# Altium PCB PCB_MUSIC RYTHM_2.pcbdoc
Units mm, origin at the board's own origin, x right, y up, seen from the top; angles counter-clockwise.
Board outline 75.42 x 40.06 mm, 2 copper layers (Top Layer, Bottom Layer); 25 components, 17 nets, 57 pads, 0 vias.
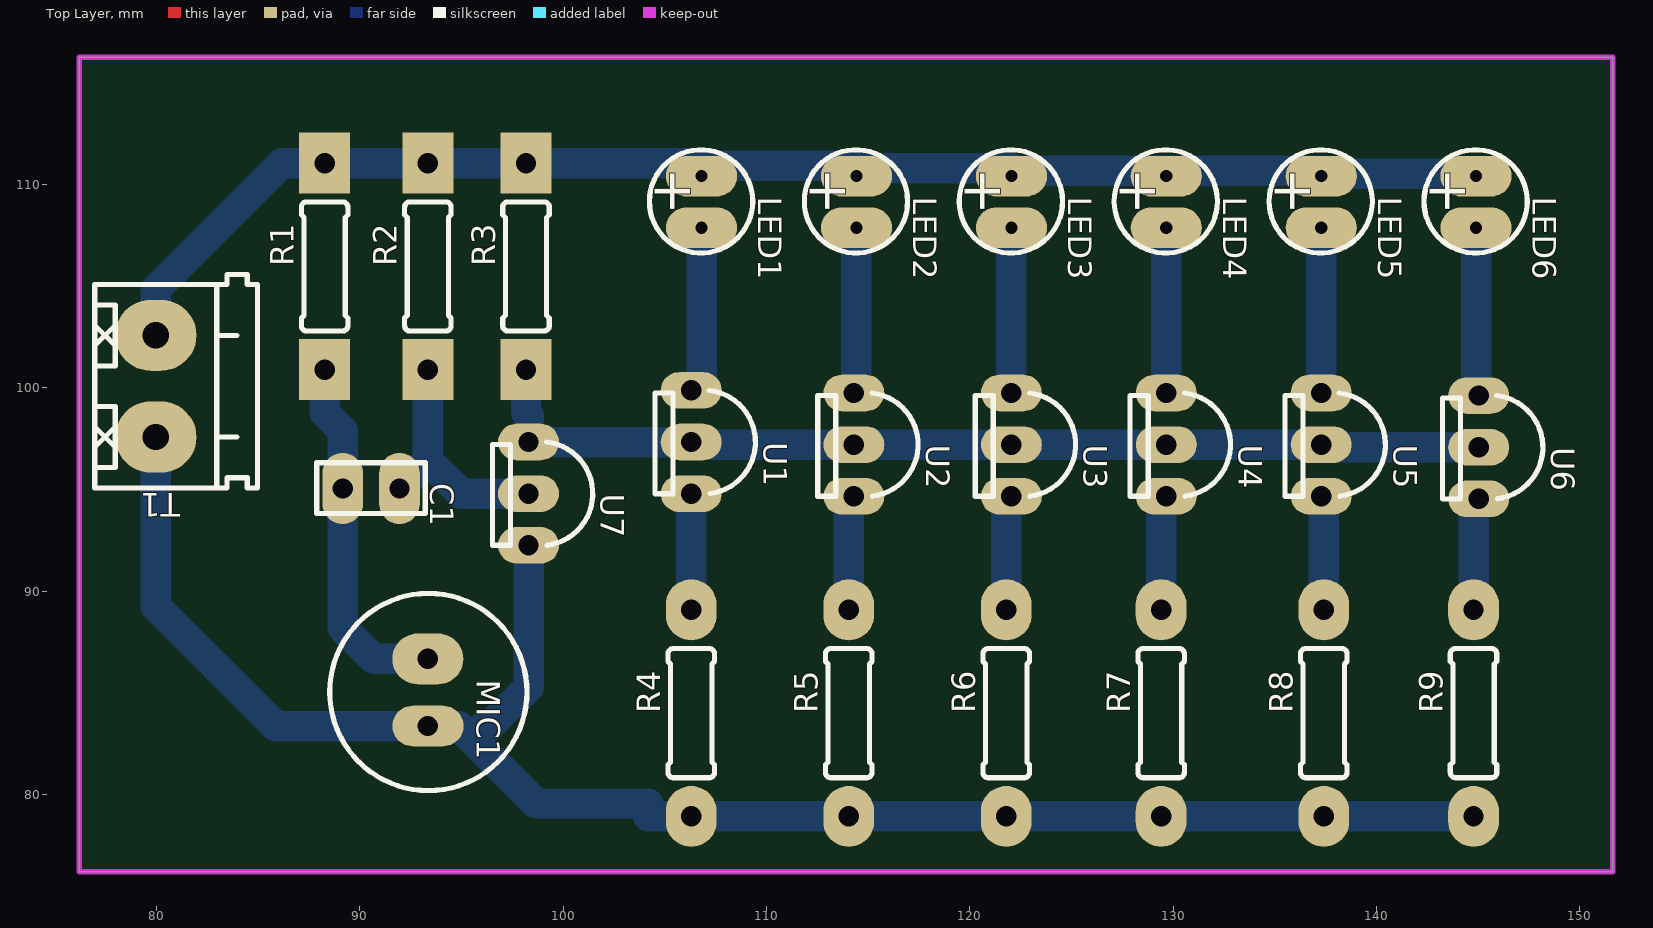
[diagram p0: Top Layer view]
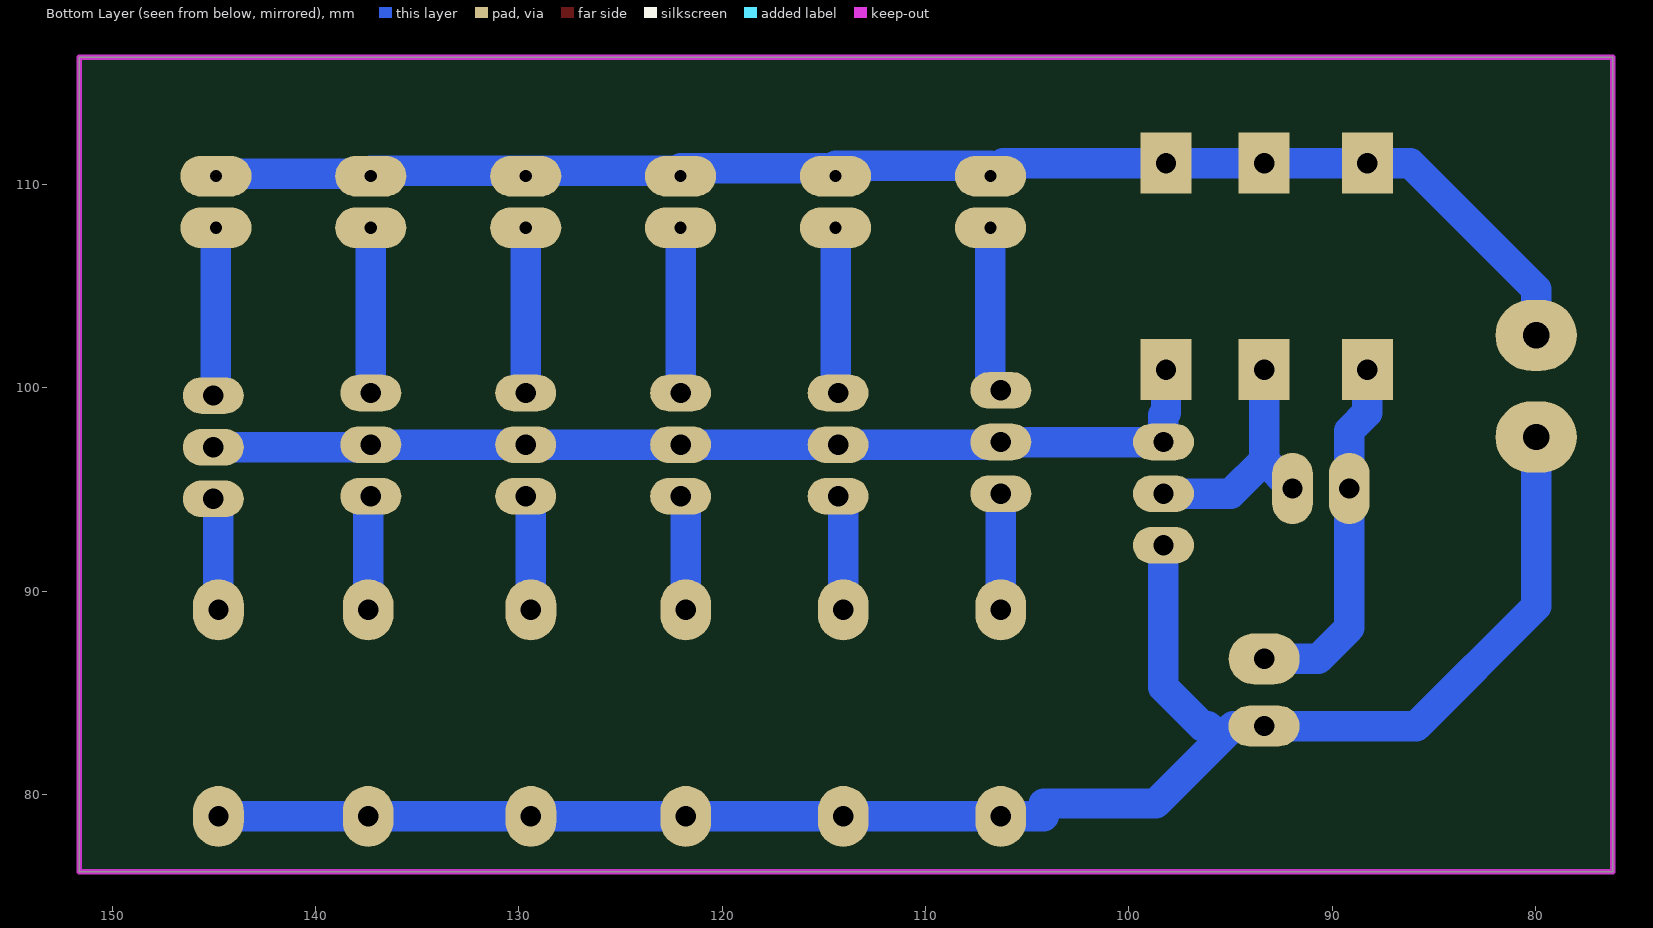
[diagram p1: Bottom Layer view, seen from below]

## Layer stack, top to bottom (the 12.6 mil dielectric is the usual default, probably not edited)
Top Layer: signal copper (thickness not stored)
Dielectric: dielectric 0.32, FR-4, Dk 4.8
Bottom Layer: signal copper (thickness not stored)

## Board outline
76.2,116.261 151.623,116.261 151.623,76.2 76.2,76.2

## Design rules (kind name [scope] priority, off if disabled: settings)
BoardOutlineClearance Default [All] p0: genericclearance=0.254 ignorepadtopadclearanceinfootprint=FALSE except(0: Region-CutoutEdge Arc-SplitContinuation Track-SplitContinuation SMDPad-SplitContinuation THPad-SplitContinuation Via-SplitContinuation Fill-SplitContinuation Poly-SplitContinuation Region-SplitContinuation Text-SplitContinuation; 0.5: Track-OutlineEdge SMDPad-OutlineEdge THPad-OutlineEdge Via-OutlineEdge Fill-OutlineEdge Region-OutlineEdge Poly-OutlineEdge Text-OutlineEdge Sheet-OutlineEdge Hole-OutlineEdge Track-CutoutEdge SMDPad-CutoutEdge THPad-CutoutEdge Via-CutoutEdge Fill-CutoutEdge Poly-CutoutEdge Text-CutoutEdge Sheet-CutoutEdge Hole-CutoutEdge)
Clearance Default [All] p1: gap=0.178 ignorepadtopadclearanceinfootprint=FALSE except(0: Region-Region; 0.5: Track-Track SMDPad-Track THPad-Track Via-Track Fill-Track Region-Track Poly-Track Text-Track Sheet-Track Hole-Track Track-SMDPad SMDPad-SMDPad THPad-SMDPad Via-SMDPad Fill-SMDPad Region-SMDPad Poly-SMDPad Text-SMDPad Sheet-SMDPad Hole-SMDPad Track-THPad SMDPad-THPad THPad-THPad Via-THPad Fill-THPad Region-THPad Poly-THPad Text-THPad Sheet-THPad Hole-THPad Track-Via SMDPad-Via THPad-Via Via-Via Fill-Via Region-Via Poly-Via Text-Via Sheet-Via Hole-Via Track-Fill SMDPad-Fill THPad-Fill Via-Fill Fill-Fill Region-Fill Poly-Fill Text-Fill Sheet-Fill Hole-Fill Track-Region SMDPad-Region THPad-Region Via-Region Fill-Region Poly-Region Text-Region Sheet-Region Hole-Region Track-Poly SMDPad-Poly THPad-Poly Via-Poly Fill-Poly Region-Poly Poly-Poly Text-Poly Sheet-Poly Hole-Poly Track-Text SMDPad-Text THPad-Text Via-Text Fill-Text Region-Text Poly-Text Text-Text Sheet-Text Hole-Text Track-Sheet SMDPad-Sheet THPad-Sheet Via-Sheet Fill-Sheet Region-Sheet Poly-Sheet Text-Sheet Sheet-Sheet Hole-Sheet Track-Hole SMDPad-Hole THPad-Hole Via-Hole Fill-Hole Region-Hole Poly-Hole Text-Hole Sheet-Hole Hole-Hole)
PasteMaskExpansion Common [All] p1: expansion=0
PlaneConnect Default [All] p1: planeconnectstyle=Relief reliefexpansion=0.508 reliefentries=4 reliefconductorwidth=0 reliefairgap=0.025
PolygonConnect Default [All] p1: connectstyle=Relief reliefentries=4 reliefconductorwidth=0 polygonreliefangle="90 Angle" airgapwidth=10
RoutingVias Default [All] p1: viastyle="Through Hole" holewidth=12.008000000000001 minholewidth=12.008000000000001 maxholewidth=2362 width=24.016000000000002 minwidth=24.016000000000002 maxwidth=3938
SolderMaskExpansion Common [All] p1: useseparateexpansions=TRUE expansion=2 expansionbottom=2
Width Default [All] p1: maxlimit=1000 minlimit=59 preferedwidth=59

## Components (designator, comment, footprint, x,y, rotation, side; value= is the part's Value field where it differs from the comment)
C1 "100nF" "CERAMIC - 104" 89.154,95.052 r270 top
LED1 "LED_5MM COPY COPY" LED-5MM-5MM 104.267,107.879 r270 top
LED2 "LED_5MM COPY COPY" LED-5MM-5MM 111.887,107.879 r270 top
LED3 "LED_5MM COPY COPY" LED-5MM-5MM 119.507,107.879 r270 top
LED4 "LED_5MM COPY COPY" LED-5MM-5MM 127.127,107.879 r270 top
LED5 "LED_5MM COPY COPY" LED-5MM-5MM 134.747,107.879 r270 top
LED6 "LED_5MM COPY COPY" LED-5MM-5MM 142.367,107.879 r270 top
MIC1 "Microphone" MICROPHONE 93.345,85.019 r90 top
R1 "10k" RTH025W#1 88.265,105.974 r90 top
R2 "1M" RTH025W#1 93.345,105.974 r90 top
R3 "10k" RTH025W#1 98.171,105.974 r90 top
R4 "1k" RTH025W#2 106.299,84.003 r90 top
R5 "1k" RTH025W#2 114.046,84.003 r90 top
R6 "1k" RTH025W#2 121.793,84.003 r90 top
R7 "1k" RTH025W#2 129.413,84.003 r90 top
R8 "1k" RTH025W#2 137.414,84.003 r90 top
R9 "1k" RTH025W#2 144.78,84.003 r90 top
T1 "SCREW TERMINAL COPY" "M02 SCREW TERMINAL 5MM 10X8MM" 84.963,105.085 r180 top
U1 "BC547" "TRANS NPN" 107.061,97.338 r270 top
U2 "BC547" "TRANS NPN" 115.062,97.211 r270 top
U3 "BC547" "TRANS NPN" 122.809,97.211 r270 top
U4 "BC547" "TRANS NPN" 130.429,97.211 r270 top
U5 "BC547" "TRANS NPN" 138.049,97.211 r270 top
U6 "BC547" "TRANS NPN" 145.796,97.084 r270 top
U7 "BC547" "TRANS NPN" 99.06,94.798 r270 top

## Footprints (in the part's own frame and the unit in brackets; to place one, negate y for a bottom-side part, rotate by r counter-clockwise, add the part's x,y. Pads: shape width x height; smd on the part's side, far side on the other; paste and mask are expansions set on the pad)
"CERAMIC - 104" [mm]
  oval 3.5x2 hole 1: 1(0,0) 2(0,2.794)
  silkscreen extent -1.27,-1.28 1.23,4.06
LED-5MM-5MM [mm]
  oval 2x3.5 hole 0.6: 1(-2.54,2.54) 2(0,2.54)
  silkscreen extent -3.83,-0.02 1.24,5.06
"M02 SCREW TERMINAL 5MM 10X8MM" [mm]
  oval 4x3.5 hole 1.3: 1(5,7.5) 2(5,2.5)
  silkscreen extent 0,-0.5 8,10
MICROPHONE [mm]
  oval 2.5x3.5 hole 1: 1(1.651,0)
  oval 2x3.5 hole 1: 2(-1.651,0)
  silkscreen extent -4.83,-4.87 4.87,4.83
RTH025W#1 [mm]
  rect 3x2.5 hole 1: 1(-5.08,0) 2(5.08,0)
  silkscreen extent -3.17,-1.14 3.17,1.14
RTH025W#2 [mm]
  oval 3x2.5 hole 1: 1(-5.08,0) 2(5.08,0)
  silkscreen extent -3.17,-1.14 3.17,1.14
"TRANS NPN" [mm]
  oval 1.8x3 hole 1: 1(-2.54,-0.762) 2(0,-0.762) 3(2.54,-0.762)
  silkscreen extent -2.54,-2.54 2.54,2.39

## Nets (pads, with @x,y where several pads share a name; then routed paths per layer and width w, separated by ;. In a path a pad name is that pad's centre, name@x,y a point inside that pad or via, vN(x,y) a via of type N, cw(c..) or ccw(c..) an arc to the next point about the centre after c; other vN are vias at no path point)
C1_1: C1.1 MIC1.1 R1.1 | length 17.9
  Bottom Layer w1.5: R1.1 88.265,99.841 88.265,98.787 89.154,97.898 C1.1 89.154,88.194 90.678,86.67 MIC1.1
GND: MIC1.2 R4.1 R5.1 R6.1 R7.1 R8.1 R9.1 T1.1 U7.3 | length 88
  Bottom Layer w1.5: T1.1 79.963,89.257 85.852,83.368 MIC1.2 94.869,83.368 98.679,79.558 104.193,79.558 ; 95.499,82.738 96.129,83.368 96.393,83.368 98.298,85.273 U7.3 ; 104.193,78.923 R4.1 R5.1 R6.1 R7.1 R8.1 R9.1
LED1_2: LED1.2 U1.1 | length 8.2
  Bottom Layer w1.5: U1.1 106.807,100.386 LED1.2
LED2_2: LED2.2 U2.1 | length 8.2
  Bottom Layer w1.5: U2.1 114.427,99.878 LED2.2
LED3_2: LED3.2 U3.1 | length 8.1
  Bottom Layer w1.5: U3.1 LED3.2
LED4_2: LED4.2 U4.1 | length 8.1
  Bottom Layer w1.5: U4.1 LED4.2
LED5_2: LED5.2 U5.1 | length 8.1
  Bottom Layer w1.5: U5.1 LED5.2
LED6_2: LED6.2 U6.1 | length 8.3
  Bottom Layer w1.5: LED6.2 144.907,99.751 U6.1
U1_3: R4.2 U1.3 | length 5.7
  Bottom Layer w1.5: R4.2 U1.3
U2_3: R5.2 U2.3 | length 5.7
  Bottom Layer w1.5: R5.2 114.046,94.417 U2.3
U3_3: R6.2 U3.3 | length 5.7
  Bottom Layer w1.5: R6.2 121.793,94.417 U3.3
U4_3: R7.2 U4.3 | length 5.7
  Bottom Layer w1.5: R7.2 129.413,94.417 U4.3
U5_3: R8.2 U5.3 | length 5.6
  Bottom Layer w1.5: U5.3 137.414,94.544 R8.2
U6_3: R9.2 U6.3 | length 5.6
  Bottom Layer w1.5: R9.2 144.78,94.29 U6.3
U7_1: R3.1 U1.2 U2.2 U3.2 U4.2 U5.2 U6.2 U7.1 | length 50.4
  Bottom Layer w1.5: R3.1 98.171,98.787 98.298,98.66 U7.1 U1.2 106.426,97.211 U2.2 U3.2 U4.2 U5.2 137.414,97.084 U6.2
U7_2: C1.2 R2.1 U7.2 | length 12.1
  Bottom Layer w1.5: C1.2 93.345,96.449 ; R2.1 93.345,96.449 ; U7.2 94.996,94.798 93.345,96.449
VCC: LED1.1 LED2.1 LED3.1 LED4.1 LED5.1 LED6.1 R1.2 R2.2 R3.2 T1.2 | length 70
  Bottom Layer w1.5: T1.2 79.963,104.858 86.159,111.054 R1.2 R2.2 R3.2 106.172,111.054 LED1.1 ; LED1.1@106.807,110.927 109.624,110.927 LED2.1@114.427,110.927 ; LED2.1@114.427,110.8 LED3.1@122.047,110.8 ; LED3.1@122.047,110.673 129.667,110.673 LED5.1@137.287,110.673 ; LED5.1@137.287,110.546 LED6.1@144.907,110.546

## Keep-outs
Board Outline Layer:
  the board outline again, w0.254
